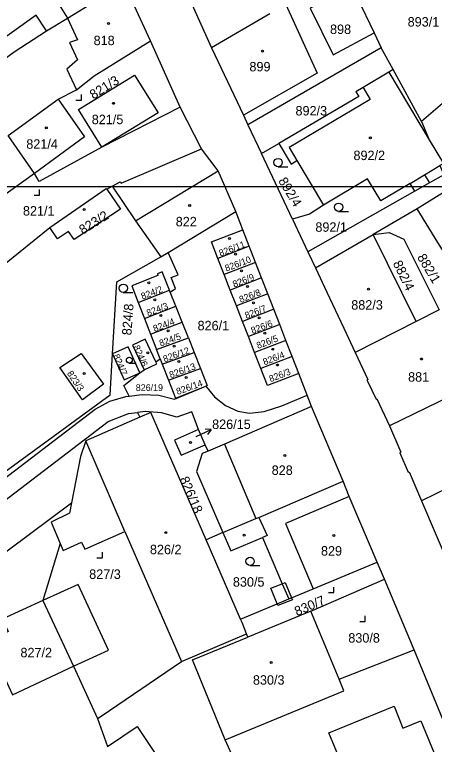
# Model space of a CAD drawing. Extents: x -496682 to -495907, y -1088575 to -1088018.
# Drawn here: x -496271.6 to -496196, y -1088264.6 to -1088133.3 of the extents above; entities that cross this region are included whole.
import ezdxf

# ---------------------------------------------------------------- set-up
doc = ezdxf.new("R2010")
doc.units = 0
for name, color, linetype in [('Hranice parcel', 7, 'Continuous'), ('Parcelní čísla', 7, 'Continuous'), ('Pop  PČ popisy', 7, 'Continuous'), ('Vnitřní kresba', 7, 'Continuous'), ('Vrstva 63', 7, 'Continuous'), ('Značky budov', 7, 'Continuous'), ('Značky kultur', 7, 'Continuous')]:
    doc.layers.add(name, color=color, linetype=linetype)

msp = doc.modelspace()

# ---------------------------------------------------------------- linework, layer by layer
at = {"layer": 'Hranice parcel'}
for p, q in [((-496243.59, -1088122.72), (-496236.14, -1088139.28)), ((-496247.14, -1088138.02), (-496251.99, -1088127.48)), ((-496210.87, -1088128.14), (-496206.88, -1088136.59)), ((-496264.2, -1088130.52), (-496262.1, -1088133.95)), ((-496262.1, -1088133.95), (-496257, -1088130.8)), ((-496225.65, -1088133.15), (-496236.14, -1088139.28)), ((-496265.89, -1088136.18), (-496262.1, -1088133.95)), ((-496206.88, -1088136.59), (-496205.62, -1088139.25)), ((-496241.8, -1088149.94), (-496247.14, -1088138.02)), ((-496205.62, -1088139.25), (-496229.59, -1088153.09)), ((-496203.46, -1088143.17), (-496205.62, -1088139.25)), ((-496198.32, -1088152.5), (-496203.46, -1088143.17)), ((-496187.08, -1088142.78), (-496198.32, -1088152.5)), ((-496263.79, -1088148.47), (-496260.45, -1088146.79)), ((-496272.8, -1088155.01), (-496263.79, -1088148.47)), ((-496237.95, -1088157.41), (-496241.8, -1088149.94)), ((-496229.59, -1088153.09), (-496227.14, -1088158.28)), ((-496268.02, -1088161.9), (-496272.8, -1088155.01)), ((-496227.14, -1088158.28), (-496224.02, -1088156.48)), ((-496221.59, -1088170.07), (-496227.14, -1088158.28)), ((-496255.04, -1088164.71), (-496254.07, -1088164.17)), ((-496199.54, -1088165.08), (-496218.8, -1088175.99)), ((-496243.96, -1088176.09), (-496231.8, -1088168.7)), ((-496230.52, -1088171.99), (-496231.8, -1088168.7)), ((-496199.12, -1088168.24), (-496207.04, -1088172.83)), ((-496221.59, -1088170.07), (-496218.8, -1088175.99)), ((-496278.83, -1088182.48), (-496265.29, -1088171.61)), ((-496229.35, -1088174.98), (-496230.52, -1088171.99)), ((-496217.42, -1088178.85), (-496207.04, -1088172.83)), ((-496199.29, -1088188.52), (-496207.04, -1088172.83)), ((-496229.35, -1088174.98), (-496234.99, -1088177.17)), ((-496228.23, -1088177.87), (-496229.35, -1088174.98)), ((-496245.26, -1088176.88), (-496243.96, -1088176.09)), ((-496218.8, -1088175.99), (-496217.42, -1088178.85)), ((-496233.87, -1088180.06), (-496234.99, -1088177.17)), ((-496228.23, -1088177.87), (-496233.87, -1088180.06)), ((-496227.14, -1088180.67), (-496228.23, -1088177.87)), ((-496232.78, -1088182.86), (-496233.87, -1088180.06)), ((-496227.14, -1088180.67), (-496232.78, -1088182.86)), ((-496226.03, -1088183.51), (-496227.14, -1088180.67)), ((-496249.36, -1088185.06), (-496243.73, -1088182.86)), ((-496243.63, -1088183.24), (-496243.73, -1088182.86)), ((-496242.58, -1088185.76), (-496243.63, -1088183.24)), ((-496231.67, -1088185.7), (-496232.78, -1088182.86)), ((-496226.03, -1088183.51), (-496231.67, -1088185.7)), ((-496224.95, -1088186.28), (-496226.03, -1088183.51)), ((-496249.36, -1088185.06), (-496248.24, -1088187.94)), ((-496248.24, -1088187.94), (-496242.58, -1088185.76)), ((-496241.45, -1088188.63), (-496242.58, -1088185.76)), ((-496230.59, -1088188.48), (-496231.67, -1088185.7)), ((-496224.95, -1088186.28), (-496230.59, -1088188.48)), ((-496223.88, -1088189.03), (-496224.95, -1088186.28)), ((-496195.13, -1088186.39), (-496199.29, -1088188.52)), ((-496248.24, -1088187.94), (-496247.13, -1088190.79)), ((-496229.52, -1088191.23), (-496230.59, -1088188.48)), ((-496199.29, -1088188.52), (-496210.3, -1088194.11)), ((-496247.13, -1088190.79), (-496241.45, -1088188.63)), ((-496240.33, -1088191.44), (-496241.45, -1088188.63)), ((-496223.88, -1088189.03), (-496229.52, -1088191.23)), ((-496222.77, -1088191.9), (-496223.88, -1088189.03)), ((-496247.13, -1088190.79), (-496246.04, -1088193.57)), ((-496246.04, -1088193.57), (-496240.33, -1088191.44)), ((-496240.33, -1088191.44), (-496239.28, -1088194.09)), ((-496228.41, -1088194.09), (-496229.52, -1088191.23)), ((-496222.77, -1088191.9), (-496228.41, -1088194.09)), ((-496221.65, -1088194.78), (-496222.77, -1088191.9)), ((-496245.4, -1088195.22), (-496246.04, -1088193.57)), ((-496245.02, -1088196.2), (-496239.28, -1088194.09)), ((-496239.28, -1088194.09), (-496238.15, -1088196.96)), ((-496227.29, -1088196.97), (-496228.41, -1088194.09)), ((-496221.65, -1088194.78), (-496227.29, -1088196.97)), ((-496220.45, -1088197.86), (-496221.65, -1088194.78)), ((-496246.18, -1088195.79), (-496245.4, -1088195.22)), ((-496245.4, -1088195.22), (-496245.02, -1088196.2)), ((-496245.02, -1088196.2), (-496243.91, -1088199.04)), ((-496249.06, -1088197.72), (-496248.29, -1088197.2)), ((-496243.91, -1088199.04), (-496238.15, -1088196.96)), ((-496218.94, -1088201.74), (-496220.45, -1088197.86)), ((-496218.13, -1088203.82), (-496218.94, -1088201.74)), ((-496212.43, -1088217.26), (-496218.13, -1088203.82)), ((-496249.48, -1088204.87), (-496249.04, -1088205.74)), ((-496237.31, -1088210.69), (-496238.5, -1088207.96)), ((-496236.79, -1088211.83), (-496237.31, -1088210.69)), ((-496198.35, -1088220.77), (-496191.24, -1088237.47)), ((-496234.09, -1088226.5), (-496237.12, -1088227.8)), ((-496230.93, -1088242.07), (-496237.12, -1088227.8)), ((-496263.4, -1088228.45), (-496266.56, -1088238.74)), ((-496205.03, -1088234.9), (-496206.35, -1088231.82)), ((-496218.27, -1088240.64), (-496205.03, -1088234.9)), ((-496199.66, -1088247.57), (-496205.03, -1088234.9)), ((-496218.27, -1088240.64), (-496229.63, -1088245.28)), ((-496213.15, -1088252.87), (-496218.27, -1088240.64)), ((-496241.58, -1088249.7), (-496229.85, -1088244.73)), ((-496229.63, -1088245.28), (-496229.85, -1088244.73)), ((-496213.15, -1088252.87), (-496199.66, -1088247.57)), ((-496188.02, -1088275.91), (-496199.66, -1088247.57)), ((-496261.03, -1088250.54), (-496256.69, -1088259.96)), ((-496256.69, -1088259.96), (-496254.9, -1088264.97)), ((-496224.27, -1088284.4), (-496233.69, -1088263.8))]:
    msp.add_line(p, q, dxfattribs=at)
for points in [[(-496210.87, -1088128.14), (-496218.36, -1088132.15), (-496214.27, -1088140.54), (-496206.88, -1088136.59)], [(-496265.89, -1088136.18), (-496267.72, -1088133.38), (-496298.45, -1088155.33)], [(-496262.1, -1088133.95), (-496260.32, -1088137.8), (-496261.74, -1088138.32), (-496260.3, -1088141.44), (-496262.22, -1088143.07), (-496260.45, -1088146.79)], [(-496295.42, -1088158.88), (-496286.46, -1088150.74), (-496280.26, -1088146.23), (-496271.7, -1088140.01), (-496265.89, -1088136.18)], [(-496260.45, -1088146.79), (-496257.27, -1088144.28), (-496247.14, -1088138.02)], [(-496236.14, -1088139.28), (-496230.41, -1088151.36), (-496229.59, -1088153.09)], [(-496203.46, -1088143.17), (-496204.25, -1088143.65), (-496208.86, -1088146.39), (-496210.14, -1088147.15), (-496209.63, -1088148), (-496224.02, -1088156.48)], [(-496250.04, -1088144.19), (-496245.79, -1088150.95), (-496255.91, -1088157.15), (-496260.09, -1088150.37), (-496250.04, -1088144.19)], [(-496263.79, -1088148.47), (-496259.06, -1088155.27), (-496268.02, -1088161.9)], [(-496241.8, -1088149.94), (-496255.91, -1088157.15), (-496267.18, -1088163.34), (-496268.02, -1088161.9)], [(-496198.32, -1088152.5), (-496196.96, -1088155.81), (-496194.39, -1088160.08), (-496195.03, -1088160.46), (-496194.34, -1088162.14), (-496196.89, -1088163.58), (-496199.54, -1088165.08)], [(-496224.02, -1088156.48), (-496221.81, -1088160.18), (-496220.77, -1088159.55), (-496215.96, -1088167.6)], [(-496254.07, -1088164.17), (-496252.59, -1088163.36), (-496252.44, -1088163.62), (-496237.95, -1088157.41)], [(-496231.8, -1088168.7), (-496234.94, -1088161.4), (-496237.95, -1088157.41)], [(-496182.92, -1088158.15), (-496186.17, -1088160.2), (-496199.12, -1088168.24)], [(-496268.02, -1088161.9), (-496282.4, -1088172.11), (-496281.47, -1088173.42), (-496283.92, -1088175.15)], [(-496199.54, -1088165.08), (-496200.38, -1088163.65), (-496205.67, -1088166.81), (-496208.04, -1088162.84), (-496215.96, -1088167.6)], [(-496265.29, -1088171.61), (-496255.13, -1088164.58), (-496255.04, -1088164.71)], [(-496255.04, -1088164.71), (-496252.56, -1088168.29), (-496260.9, -1088173.75), (-496261.91, -1088172.29), (-496263.88, -1088173.65), (-496265.29, -1088171.61)], [(-496254.07, -1088164.17), (-496249.82, -1088170.42), (-496245.26, -1088176.88)], [(-496215.96, -1088167.6), (-496218.53, -1088169.21), (-496221.59, -1088170.07)], [(-496193.41, -1088177.4), (-496195.37, -1088174.27), (-496199.12, -1088168.24)], [(-496234.99, -1088177.17), (-496236.17, -1088174.19), (-496230.52, -1088171.99)], [(-496207.04, -1088172.83), (-496204.16, -1088172.47), (-496201.5, -1088173.7), (-496195.13, -1088186.39)], [(-496243.63, -1088183.24), (-496242.63, -1088182.58), (-496243.44, -1088180.59), (-496242.16, -1088180.08), (-496243.96, -1088176.09)], [(-496253.97, -1088194.3), (-496253.21, -1088181.35), (-496245.26, -1088176.88)], [(-496217.42, -1088178.85), (-496215.39, -1088183.24), (-496212.35, -1088189.69), (-496210.3, -1088194.11)], [(-496243.73, -1088182.86), (-496244.92, -1088179.86), (-496245.04, -1088179.57), (-496245.9, -1088179.95), (-496245.8, -1088180.2), (-496250.53, -1088182.08), (-496249.36, -1088185.06)], [(-496246.18, -1088195.79), (-496248.08, -1088191.7), (-496250.36, -1088192.76), (-496248.29, -1088197.2)], [(-496249.06, -1088197.72), (-496251.15, -1088193.04), (-496253.97, -1088194.3)], [(-496311.81, -1088243.59), (-496254.42, -1088201.7), (-496253.97, -1088194.3)], [(-496263.48, -1088196.77), (-496259.62, -1088194.28), (-496255.59, -1088199.81)], [(-496253.97, -1088194.3), (-496251.88, -1088198.98), (-496249.06, -1088197.72)], [(-496210.3, -1088194.11), (-496208.02, -1088198.95), (-496208.16, -1088199.02), (-496208.06, -1088199.23), (-496206.51, -1088202.51), (-496206.37, -1088202.45), (-496204.1, -1088207.28)], [(-496248.29, -1088197.2), (-496246.02, -1088196.14), (-496246.18, -1088195.79)], [(-496255.59, -1088199.81), (-496259.41, -1088202.59), (-496263.48, -1088196.77)], [(-496250.98, -1088201.92), (-496251.95, -1088200), (-496249.06, -1088197.72)], [(-496238.15, -1088196.96), (-496236.93, -1088200.02), (-496237.18, -1088200.12)], [(-496220.45, -1088197.86), (-496226.09, -1088200.05), (-496227.29, -1088196.97)], [(-496185.54, -1088197.33), (-496188.66, -1088199.81), (-496204.1, -1088207.28)], [(-496243.91, -1088199.04), (-496242.64, -1088202.29), (-496237.18, -1088200.12)], [(-496250.98, -1088201.92), (-496248.64, -1088201.63), (-496245.64, -1088201.74), (-496242.85, -1088202.47), (-496237.18, -1088200.12)], [(-496237.18, -1088200.12), (-496235.63, -1088202.06), (-496233.62, -1088203.63), (-496231.44, -1088204.65), (-496229.32, -1088205), (-496226.65, -1088204.68), (-496223.49, -1088203.7), (-496218.94, -1088201.74)], [(-496310.18, -1088244.79), (-496257.12, -1088204.31), (-496254.49, -1088202.87), (-496251.61, -1088202), (-496250.98, -1088201.92)], [(-496218.13, -1088203.82), (-496233.8, -1088210.57), (-496236.79, -1088211.83)], [(-496307.55, -1088246.72), (-496254.8, -1088206.49), (-496251.12, -1088205.07), (-496249.48, -1088204.87)], [(-496238.5, -1088207.96), (-496239.73, -1088204.77), (-496242.39, -1088205.73), (-496245.16, -1088204.93), (-496248.13, -1088204.71), (-496249.48, -1088204.87)], [(-496237.12, -1088227.8), (-496247.06, -1088204.88), (-496249.04, -1088205.74)], [(-496249.04, -1088205.74), (-496258.79, -1088209.96), (-496259.78, -1088212.78), (-496261.37, -1088221.14)], [(-496238.5, -1088207.96), (-496242.81, -1088209.83), (-496241.65, -1088212.57), (-496237.31, -1088210.69)], [(-496204.1, -1088207.28), (-496202.07, -1088212.04), (-496202.25, -1088212.12), (-496200.73, -1088215.63), (-496200.57, -1088215.56), (-496198.35, -1088220.77)], [(-496236.79, -1088211.83), (-496237.87, -1088212.28), (-496238.84, -1088215.51), (-496234.09, -1088226.5)], [(-496179.86, -1088211.45), (-496182.82, -1088213.25), (-496186.02, -1088214.8), (-496198.35, -1088220.77)], [(-496234.09, -1088226.5), (-496228.16, -1088223.97), (-496227.66, -1088223.76), (-496212.43, -1088217.26)], [(-496206.35, -1088231.82), (-496211.35, -1088219.97), (-496212.43, -1088217.26)], [(-496293.33, -1088244.86), (-496282.06, -1088236.51), (-496272.7, -1088229.58), (-496261.37, -1088221.14)], [(-496261.37, -1088221.14), (-496261.72, -1088222.97), (-496265.04, -1088224.59), (-496263.4, -1088228.45)], [(-496263.4, -1088228.45), (-496262.87, -1088229.7), (-496259.56, -1088228.24), (-496259, -1088229.48), (-496251.75, -1088226.32), (-496241.58, -1088249.7)], [(-496234.09, -1088226.5), (-496232.66, -1088229.8), (-496228.12, -1088227.84), (-496227, -1088227.36), (-496223.42, -1088235.69), (-496222.24, -1088238.44)], [(-496222.24, -1088238.44), (-496221.74, -1088238.24), (-496217.87, -1088236.62), (-496206.35, -1088231.82)], [(-496261.03, -1088250.54), (-496254.74, -1088247.66), (-496260.18, -1088235.84), (-496266.56, -1088238.74)], [(-496230.93, -1088242.07), (-496224.34, -1088239.32), (-496222.24, -1088238.44)], [(-496266.56, -1088238.74), (-496273.85, -1088242.06), (-496272.81, -1088244.31), (-496276.5, -1088246.03), (-496272.01, -1088255.68), (-496261.03, -1088250.54)], [(-496229.85, -1088244.73), (-496230.66, -1088242.69), (-496230.93, -1088242.07)], [(-496233.69, -1088263.8), (-496239.59, -1088249.36), (-496229.63, -1088245.28)], [(-496256.69, -1088259.96), (-496256.02, -1088259.51), (-496241.58, -1088249.7)], [(-496233.69, -1088263.8), (-496212.34, -1088254.94), (-496213.15, -1088252.87)], [(-496224.27, -1088284.4), (-496221.97, -1088283.2), (-496218.31, -1088281.3), (-496217.38, -1088283.04), (-496208.49, -1088278.31), (-496215.03, -1088262.55), (-496203.26, -1088257.73), (-496201.7, -1088261.7), (-496198.45, -1088260.34), (-496192.96, -1088273.71), (-496196.19, -1088275), (-496194.54, -1088278.98), (-496202.44, -1088282.27), (-496202.01, -1088283.23), (-496220.05, -1088292.84)], [(-496254.9, -1088264.97), (-496249.52, -1088261.41), (-496243.33, -1088270.76)]]:
    msp.add_lwpolyline(points, dxfattribs=at)
at = {"layer": 'Pop  PČ popisy'}
for p, q in [((-496238.92, -1088209.2), (-496236.2, -1088207.93)), ((-496236.2, -1088207.93), (-496237.32, -1088207.9)), ((-496236.2, -1088207.93), (-496236.9, -1088208.81))]:
    msp.add_line(p, q, dxfattribs=at)
at = {"layer": 'Vnitřní kresba'}
for p, q in [((-496222.8, -1088131.48), (-496217.11, -1088143.84)), ((-496217.11, -1088143.84), (-496230.41, -1088151.36)), ((-496204.25, -1088143.65), (-496196.96, -1088155.81)), ((-496208.86, -1088146.39), (-496207.59, -1088148.55)), ((-496207.59, -1088148.55), (-496222.17, -1088157.19)), ((-496222.17, -1088157.19), (-496220.77, -1088159.55)), ((-496197.78, -1088162.1), (-496195.03, -1088160.46)), ((-496249.82, -1088170.42), (-496234.94, -1088161.4)), ((-496200.38, -1088163.65), (-496197.78, -1088162.1)), ((-496197.78, -1088162.1), (-496196.89, -1088163.58)), ((-496251.75, -1088226.32), (-496258.79, -1088209.96)), ((-496233.8, -1088210.57), (-496228.16, -1088223.97)), ((-496211.35, -1088219.97), (-496222.82, -1088224.87)), ((-496227.66, -1088223.76), (-496226.14, -1088226.99)), ((-496222.82, -1088224.87), (-496217.87, -1088236.62)), ((-496226.14, -1088226.99), (-496227, -1088227.36)), ((-496225.15, -1088236.38), (-496223.42, -1088235.69)), ((-496223.42, -1088235.69), (-496222.89, -1088235.48)), ((-496222.89, -1088235.48), (-496221.74, -1088238.24)), ((-496225.49, -1088236.52), (-496225.15, -1088236.38)), ((-496224.34, -1088239.32), (-496225.49, -1088236.52)), ((-496221.74, -1088238.24), (-496221.6, -1088238.57)), ((-496266.56, -1088238.74), (-496261.03, -1088250.54)), ((-496224.21, -1088239.64), (-496224.34, -1088239.32)), ((-496221.6, -1088238.57), (-496224.21, -1088239.64))]:
    msp.add_line(p, q, dxfattribs=at)
at = {"layer": 'Vrstva 63'}
msp.add_lwpolyline([(-496137.35, -1088164.24), (-496137.35, -1088461.24), (-496557.35, -1088461.24), (-496557.35, -1088164.24)], close=True, dxfattribs=at)
at = {"layer": 'Značky budov'}
for centre in [(-496254.72, -1088134.89), (-496226.95, -1088139.88), (-496253.83, -1088149.25), (-496265.91, -1088153.67), (-496207.55, -1088155.47), (-496240.09, -1088167.63), (-496259.11, -1088168.33), (-496232.92, -1088173.59), (-496231.86, -1088176.41), (-496230.74, -1088179.41), (-496247.44, -1088181.54), (-496229.68, -1088182.23), (-496207.89, -1088182.71), (-496246.38, -1088184.59), (-496228.62, -1088185.16), (-496245.26, -1088187.41), (-496227.57, -1088187.87), (-496243.95, -1088190.17), (-496226.57, -1088190.63), (-496242.9, -1088192.93), (-496225.14, -1088193.51), (-496247.63, -1088194.14), (-496198.35, -1088195.25), (-496242.03, -1088195.69), (-496224.27, -1088196.33), (-496259.11, -1088197.88), (-496240.72, -1088198.57), (-496239.96, -1088210.28), (-496222.97, -1088212.61), (-496244.39, -1088226.5), (-496230.3, -1088226.97), (-496214.11, -1088227), (-496225.43, -1088249.85)]:
    msp.add_circle(centre, 0.175, dxfattribs=at)
at = {"layer": 'Značky kultur'}
for p, q in [((-496259.58, -1088148.67), (-496259.58, -1088147.67)), ((-496260.58, -1088148.67), (-496259.58, -1088148.67)), ((-496224.16, -1088160.66), (-496222.41, -1088160.66)), ((-496267.11, -1088165.77), (-496267.11, -1088164.77)), ((-496268.11, -1088165.77), (-496267.11, -1088165.77)), ((-496213.26, -1088168.69), (-496211.51, -1088168.69)), ((-496252.05, -1088183.27), (-496250.3, -1088183.27)), ((-496250.96, -1088195.98), (-496249.73, -1088195.98)), ((-496255.82, -1088231.02), (-496255.82, -1088230.02)), ((-496256.82, -1088231.02), (-496255.82, -1088231.02)), ((-496229.21, -1088232.41), (-496227.46, -1088232.41)), ((-496214.11, -1088237.3), (-496214.11, -1088236.3)), ((-496215.11, -1088237.3), (-496214.11, -1088237.3)), ((-496208.46, -1088242.47), (-496208.46, -1088241.47)), ((-496209.46, -1088242.47), (-496208.46, -1088242.47))]:
    msp.add_line(p, q, dxfattribs=at)
for centre, radius in [((-496224.16, -1088159.91), 0.75), ((-496213.26, -1088167.94), 0.75), ((-496252.05, -1088182.52), 0.75), ((-496250.96, -1088195.45), 0.525), ((-496229.21, -1088231.66), 0.75)]:
    msp.add_circle(centre, radius, dxfattribs=at)

# ---------------------------------------------------------------- texts
at = {"layer": 'Parcelní čísla'}
for s, height, p in [('893/1', 1.7, (-496200.83, -1088135.43)), ('898', 1.7, (-496214.81, -1088136.77)), ('818', 1.7, (-496257.39, -1088138.78)), ('899', 1.7, (-496229.33, -1088143.5)), ('892/3', 1.7, (-496221.03, -1088151.43)), ('821/5', 1.7, (-496257.73, -1088153)), ('821/4', 1.7, (-496269.52, -1088157.42)), ('892/2', 1.7, (-496210.59, -1088159.46)), ('821/1', 1.7, (-496270.12, -1088169.44)), ('822', 1.7, (-496242.6, -1088171.38)), ('892/1', 1.7, (-496217.45, -1088172.36)), ('882/3', 1.7, (-496210.99, -1088186.37)), ('826/1', 1.7, (-496238.67, -1088190.09)), ('881', 1.7, (-496200.75, -1088199.33)), ('826/19', 1.2, (-496249.8, -1088201)), ('826/15', 1.7, (-496236.05, -1088207.85)), ('828', 1.7, (-496225.32, -1088216.11)), ('826/2', 1.7, (-496247.25, -1088230.38)), ('829', 1.7, (-496216.44, -1088230.63)), ('827/3', 1.7, (-496258.19, -1088234.82)), ('830/5', 1.7, (-496232.31, -1088236.22)), ('830/8', 1.7, (-496211.52, -1088246.29)), ('827/2', 1.7, (-496270.57, -1088248.93)), ('830/3', 1.7, (-496228.7, -1088253.86))]:
    msp.add_text(s, height=height, dxfattribs=at).set_placement(p)
for s, height, rotation, p in [('821/3', 1.7, 32, (-496257.44, -1088148.59)), ('892/4', 1.7, 301, (-496224.19, -1088163.19)), ('823/2', 1.7, 32, (-496259.35, -1088172.91)), ('826/11', 1.2, 21, (-496234.55, -1088176.84)), ('826/10', 1.2, 21, (-496233.49, -1088179.56)), ('882/1', 1.7, 301, (-496199.19, -1088176.94)), ('882/4', 1.7, 296, (-496203.54, -1088178.02)), ('826/9', 1.2, 21, (-496232.08, -1088182.41)), ('824/2', 1.2, 21, (-496248.59, -1088184.6)), ('826/8', 1.2, 21, (-496230.91, -1088185.18)), ('824/8', 1.7, 86, (-496250.59, -1088191.03)), ('824/3', 1.2, 21, (-496247.59, -1088187.59)), ('826/7', 1.2, 21, (-496229.9, -1088188.05)), ('824/4', 1.2, 21, (-496246.41, -1088190.41)), ('826/6', 1.2, 21, (-496228.78, -1088190.76)), ('824/5', 1.2, 20, (-496245.31, -1088193.03)), ('826/5', 1.2, 21, (-496227.79, -1088193.46)), ('824/6', 1.2, 294, (-496250.3, -1088193.09)), ('826/12', 1.2, 20, (-496244.62, -1088195.87)), ('824/7', 1.2, 293, (-496253.92, -1088194.67)), ('826/4', 1.2, 21, (-496226.61, -1088196.4)), ('826/13', 1.2, 20, (-496243.5, -1088198.74)), ('823/3', 1.2, 304, (-496262.26, -1088197.86)), ('826/3', 1.2, 21, (-496225.52, -1088199.44)), ('826/14', 1.2, 20, (-496242.25, -1088201.74)), ('826/18', 1.7, 293, (-496241.94, -1088216.82)), ('830/7', 1.7, 23, (-496220.77, -1088241.54))]:
    msp.add_text(s, height=height, rotation=rotation, dxfattribs=at).set_placement(p)

doc.saveas('drawing.dxf')
